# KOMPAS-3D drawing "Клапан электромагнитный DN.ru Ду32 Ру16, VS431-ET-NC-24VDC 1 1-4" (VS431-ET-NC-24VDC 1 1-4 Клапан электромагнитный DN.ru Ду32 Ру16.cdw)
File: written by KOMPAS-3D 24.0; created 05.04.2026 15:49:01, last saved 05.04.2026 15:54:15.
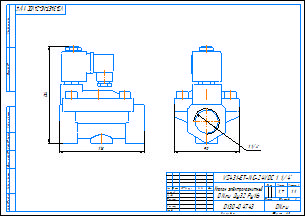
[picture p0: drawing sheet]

Document properties: c3d_UniqueCompID: ef56311e-7521-43dc-8291-0e6108b3d81d; Автор: artio; Класс точности: c; Знак неуказанной шероховатости: Шероховатость не задана; Рассекать на разрезах: Да; c3d_UniqueCompID: ef56311e-7521-43dc-8291-0e6108b3d81d; Автор: artio; Класс точности: c; Знак неуказанной шероховатости: Шероховатость не задана; Рассекать на разрезах: Да; c3d_UniqueCompID: ef56311e-7521-43dc-8291-0e6108b3d81d; Автор: artio; Класс точности: c; Знак неуказанной шероховатости: Шероховатость не задана; Рассекать на разрезах: Да; Автор: artio; Форматы листов документа: A3; Полное имя файла: VS431-ET-NC-24VDC 1 1-4 Клапан электромагнитный DN.ru Ду32 Ру16.m3d; Масса: 1.701; Наименование: Клапан электромагнитный DN.ru Ду32 Ру16; Количество листов документа: 1; Примечание: D130-04743

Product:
- Body: Тело 1  | qty 1
    Масса: 3.709873
- Part/product: Клапан электромагнитный DN.ru Ду32 Ру16  | designation VS431-ET-NC-24VDC 1 1-4
    Масса: 1.701
    Раздел спецификации: Прочие изделия
    Примечание: D130-04743
    additional columns: ef56311e-7521-43dc-8291-0e6108b3d81d; artio; c; Шероховатость не задана; Да

Views: Вид 1, Спереди
Referenced files in C:\Users\artio\OneDrive\Рабочий стол\Клапан электромагнитный DN.ru\VS431\VS431-ET-NC\: VS431-ET-NC-24VDC 3-4 Клапан электромагнитный DN.ru Ду20 Ру16.m3d, VS431-ET-NC-24VDC 1 1-4 Клапан электромагнитный DN.ru Ду32 Ру16.m3d, VS431-ET-NC-24VDC 3-4 Клапан электромагнитный DN.ru Ду20 Ру16.cdw
Referenced files in C:\Users\artio\OneDrive\Рабочий стол\Клапан электромагнитный DN.ru\VS431\VS431-ET-NC\VS431-ET-NC-24VDC\Ду32\: VS431-ET-NC-24VDC 1 1-4 Клапан электромагнитный DN.ru Ду32 Ру16.m3d
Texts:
  VS431-ET-NC-24VDC 1 1-4
  Клапан электромагнитный
  DN.ru Ду32 Ру16
  VS431-ET-NC-24VDC 1 1/4"
  VS431-ET-NC-24VDC 1 1/4"-
  Клапан электромагнитный DN.ru Ду32 Ру16
  VS431-ET-NC-24VDC 1 1-4 Клапан электромагнитный DN.ru Ду32 Ру16
Dimensions and other numbers on the sheet: 0; 3; 2; 4; 90; 1 1/4"; 1:1; 1; 1,7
